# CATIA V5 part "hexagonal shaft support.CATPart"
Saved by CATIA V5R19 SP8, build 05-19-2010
Part number: hexagonal shaft support
Bounding box of the stored display mesh (mm): x 136.206 to 167.206, y 122.6 to 137.6, z -34.388 to -6.388
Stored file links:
  G:\EU_thinkMotion\CFAO_2010\MMS_groupe1\MMS_groupe1\A reprendre\gduval\CFAO kinematic ok\hexagonal shaft support.CATPart
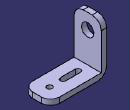
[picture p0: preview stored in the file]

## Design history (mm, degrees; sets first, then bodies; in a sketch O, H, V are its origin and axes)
Body1 (main body)
  Point1: stored without definition
  Plane1: type Offset, RefPlane xy-plane, Offset 34.5, reversed
  Plane2: stored without definition
  Line1: type Normal, RefPoint Point1, RefSkin Plane2, Start -20, End 20
  Sketch1 on Plane2, origin (136.206, 0, 0), H (0, 1, 0), V (0, 0, 1)
    line L1 (122.6, -6.3876) -> (137.6, -6.3876)
    line L2 (137.6, -6.3876) -> (137.6, -34.3876)
    line L3 (137.6, -34.3876) -> (122.6, -34.3876)
    line L4 (122.6, -34.3876) -> (122.6, -6.3876)
    reference projected point E1 (130.1, -14.68) from Point1
    reference projected point E2 (130.1, -14.68) from Point1
    distance L2 E1 = 7.5
    distance L4 E2 = 7.5
    distance L1 L3 = 28
    horizontal: L1 H, L3 H
    vertical: L2 V, L4 V
  Pad1: profile Sketch1, direction (1, 0, 0), length 3
  Sketch2 on end face of Pad1, origin (139.206, 130.1, -14.68), H (0, 1, 0), V (0, 0, 1)
    point P1 (0, 0)
    intersected point E1 (0, 0) from Line1
    coincidence: E1 P1
  Hole1: placed by Sketch2, at (139.206, 130.1, -14.68) direction (-1, 0, 0), diameter 7, through (limit type 6)
  Fillet1: radius 5, on edge [face of Pad1 from Sketch1.L1 | face of Pad1 from Sketch1.L2]; edge [face of Pad1 from Sketch1.L4 | face of Pad1 from Sketch1.L1]
  Sketch3 on end face of Pad1, origin (139.206, 0, 0), H (0, 1, 0), V (0, 0, 1)
    line L1 (122.6, -34.3876) -> (137.6, -34.3876)
    line L2 (137.6, -34.3876) -> (137.6, -31.3876)
    line L3 (137.6, -31.3876) -> (122.6, -31.3876)
    line L4 (122.6, -31.3876) -> (122.6, -34.3876)
    reference projected line E1 (122.6, -34.3876) -> (137.6, -34.3876) from edge [face of Pad1 from Sketch1.L3 | end face of Pad1]
    reference projected line E2 (137.6, -34.3876) -> (137.6, -6.3876) from edge [face of Pad1 from Sketch1.L2 | end face of Pad1]
    reference projected line E3 (122.6, -6.3876) -> (122.6, -34.3876) from edge [face of Pad1 from Sketch1.L4 | end face of Pad1]
    distance L3 L1 = 3
    horizontal: L1 H, L3 H
    vertical: L2 V, L4 V
    coincidence: L1 E1, L2 E2, L4 E3
  Pad2: profile Sketch3, direction (1, 0, 0), length 28
  Fillet2: radius 5, on edge [start face of Pad1 | face of Pad2]
  Fillet3: radius 5, on edge [face of Pad2 | end face of Pad2] (x2)
  Sketch4 on face of Pad2 from Sketch3.L3, origin (160.0157, 127.5733, -31.3876), H (1, 0, 0), V (0, 1, 0)
    point P1 (0.1903, 2.5267)
    reference projected line E1 (-43.8097, 2.5267) -> (-3.8097, 2.5267) from Line1
    reference projected line E2 (7.1903, 10.0267) -> (7.1903, -4.9733) from edge [face of Pad2 from Sketch3.L3 | end face of Pad2]
    construction line L1 (-6.5361, 1.9671) -> (-14.097, 1.9671)
    construction line L2 (-6.5361, 0.7119) -> (-14.097, 0.7119)
    construction line L3 (-14.097, 3.2223) -> (-6.5361, 3.2223)
    construction arc A1 centre (-14.097, 1.9671) radius 1.2552 from (-14.097, 0.7119) to (-14.097, 3.2223) cw
    construction arc A2 centre (-6.5361, 1.9671) radius 1.2552 from (-6.5361, 3.2223) to (-6.5361, 0.7119) cw
    distance P1 E2 = 7
    distance L1 L2 = 1.2552
    coincidence: P1 E1
    horizontal: L1 H
    tangency: A1 L2, A2 L2, A1 L3, A2 L3
  Hole2: placed by Sketch4, at (160.206, 130.1, -31.3876) direction (0, 0, -1), diameter 3, through (limit type 6)
  Sketch5 on face of Pad2 from Sketch3.L3, origin (0, 0, -31.3876), H (1, 0, 0), V (0, 1, 0)
    construction line L1 (144.5926, 130.1) -> (152.8847, 130.1)
    line L2 (144.5926, 131.6) -> (152.8847, 131.6)
    line L3 (152.8847, 128.6) -> (144.5926, 128.6)
    arc A1 centre (152.8847, 130.1) radius 1.5 from (152.8847, 131.6) to (152.8847, 128.6) cw
    arc A2 centre (144.5926, 130.1) radius 1.5 from (144.5926, 128.6) to (144.5926, 131.6) cw
    reference projected line E1 (116.206, 130.1) -> (156.206, 130.1) from Line1
    distance L1 L2 = 1.5
    horizontal: L1 H
    tangency: A1 L2, A2 L2, A1 L3, A2 L3
    coincidence: L1 E1
  Pocket1: profile Sketch5, direction (0, 0, -1), through (limit type 6)
  Point2: type OnPlane, Support Plane1, H 160.196, V 130.063, Direction (1, 0, 0)
  Line2: type Normal, RefPoint Point2, RefSkin Plane1, Start -20, End 20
